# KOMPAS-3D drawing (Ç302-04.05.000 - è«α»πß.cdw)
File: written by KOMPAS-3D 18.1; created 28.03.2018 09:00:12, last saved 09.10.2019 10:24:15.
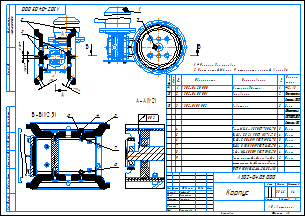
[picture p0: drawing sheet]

Sheet 1: A3, landscape

Document properties: Автор: Милов; Полное имя файла: ..\3Д ПВХ\А302-01.05.000 - Корпус.a3d; Масса: 33.4594

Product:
- Part/product: (unnamed)
  - Component: Болт М8-6gx35 ГОСТ 7805-70  | pos. 4  | Раздел спецификации: Стандартные изделия; Примечание: Нерж.
  - Component: Ловитель  | designation А302-01.05.002  | pos. 3  | Раздел спецификации: Детали; Форматы листов документа: А3; Примечание: Заим. / Фторопласт-4  / ГОСТ 10007-80 Е / Стержень @2~50
  - Component: Основание  | designation А302-04.05.001  | pos. 2  | Раздел спецификации: Детали; Форматы листов документа: А3; Примечание: Полипропилен / Стержень @2~300
  - Component: Мотор-редуктор  | designation А302-04.20.000  | pos. 1  | Раздел спецификации: Сборочные единицы; Форматы листов документа: 2xA3; Примечание: *)2xA3
  - Component: Шайба C.8.21 ГОСТ 11371-78  | pos. 5  | Раздел спецификации: Стандартные изделия; Примечание: Нерж.
  - Component: Шайба C 8.04.019 ГОСТ 6958-78  | pos. 6  | Раздел спецификации: Стандартные изделия; Примечание: Нерж.
  - Component: Шайба 8 30Х13 019 ГОСТ 6402-70  | pos. 7  | Раздел спецификации: Стандартные изделия; Примечание: Нерж.
  - Component: Гайка М8-6H.5.019 ГОСТ 5915-70  | pos. 8  | Раздел спецификации: Стандартные изделия; Примечание: Нерж
  - Component: Винт с потайной головкой и  / шестигранным углублением под ключ / ГОСТ Р ИСО 10642-М4x20-8.8-A3J  | pos. 9  | Раздел спецификации: Стандартные изделия; Примечание: Нерж.

Title block, sheet 1: Наименование: Корпус; designation: А302-04.05.000; Масса: 33,46; scale: 1:4; Количество листов документа: 1; organisation: АО «Астерион»; Форматы листов документа: A3; stored path: Z:\Мембранные насосы\Мембранный электропривод\А302-00.00.000 - ASTRA-302 (МЭ200)\Чертежи\А302-00.05.000 - Корпус.cdw; Разработал: Лифлянд; Проверил: Борисенко; Т. контр.: Лучихин; Утвердил: Григорьева

Views: Разрез В-В, Разрез А-А, Разрез Б-Б
Referenced files in \\192.168.87.28\Konstructor_doc\Мембранные насосы\Мембранный электропривод\А302-00.00.000 - ASTRA-302 (МЭ200)\3Д ПВХ\Отработка\: А302-01.05.000 - Корпус.a3d, А302-01.20.000 - Мотор-редуктор.a3d, А302-01.05.002 - Ловитель.m3d, Упор-1.m3d, Фиксатор.m3d
Referenced files in C:\Program Files\ASCON\KOMPAS-3D v18\Libs\PartLib\DATA\VAULT\methods\kompas\3d\: PLib_Check_spring_rings_GOST_13942_911.m3d, PLib_Washer_1_712.m3d, PLib_Bolt_1_900.m3d, PLib_Washer_2_712.m3d, PLib_Nut_OST92_900.m3d, PLib_Screw_DIN_7984_1500.m3d, PLib_Key_prismatic_712.m3d, PLib_Screw_ISO_10642_1500.m3d
Referenced files in D:\Мембранные насосы\Мембранный электропривод\А302-00.00.000 - ASTRA-302 (МЭ200)\3Д ПВХ\: А302-01.20.002 - Эксцентрик.m3d, FB 063 .m3d, А302-04.35.004 - Стенка.m3d, А302-04.35.003 - Опора подшиника.m3d, А302-01.20.001 - Основание.m3d, А302-01.35.000 - Фланец.a3d, А302-01.05.000 - Корпус.a3d, А302-01.05.011 - Ловитель.m3d, А302-01.05.015 - Фиксатор.m3d
Referenced files in D:\Мембранные насосы\Мембранный электропривод\А302-00.00.000 - ASTRA-302 (МЭ200)\3Д\: А302-00.35.002 - Пластина.m3d, А302-00.35.001 - Труба 140х140х4.m3d, А302-00.20.004 - Вал.m3d, А302-00.20.003 - Ползун.m3d, А302-00.05.001 - Основание.m3d
Referenced files in D:\1 ПКИ 3D\1 Крепеж стандартный\Подшипник\: Подшипник 52х25х15 62052RSH SKF.m3d, Подшипник 80х40х18 6208-2RS1 SKF.m3d
Referenced files in D:\1 ПКИ 3D\Редуктора NMRW\Редукторы\: Редуктор NMRW 063.m3d, Червячный мотор-редуктор NMRV063 АИР80.a3d
Referenced files in Z:\Мембранные насосы\Мембранный электропривод\А302-00.00.000 - ASTRA-302 (МЭ200)\3Д ПВХ\: А302-01.20.000 - Мотор-редуктор.cdw
Referenced files in \\192.168.87.28\Konstructor_doc\Мембранные насосы\Мембранный электропривод\А302-00.00.000 - ASTRA-302 (МЭ200)\3Д ПВХ\: А302-01.05.002 - Ловитель.cdw, А302-01.05.001 - Основание.m3d, А302-01.05.001 - Основание.cdw, А302-01.05.012 - Фиксатор.m3d, А302-01.05.012 - Фиксатор.cdw, А302-01.05.014 - Упор.cdw, А302-01.05.011 - Ловитель.m3d, А302-01.05.011 - Ловитель.cdw, А302-01.05.015 - Фиксатор.m3d, А302-01.05.015 - Фиксатор.cdw, А302-01.20.002 - Эксцентрик.m3d
Referenced files in \\192.168.87.28\Konstructor_doc\1 ПКИ 3D\1 Крепеж стандартный\Подшипник\: Подшипник 80х40х18 6208-2RS1 SKF.m3d, Подшипник 52х25х15 62052RSH SKF.m3d
Referenced files in D:\Мембранные насосы\Мембранный электропривод\А302-00.00.000 - ASTRA-302 (МЭ200)\3Д ПВХ\Отработка\: А302-01.20.000 - Мотор-редуктор.a3d, А302-01.05.002 - Ловитель.m3d, Фиксатор.m3d, Упор-1.m3d
Referenced files in D:\1 ПКИ 3D\Двигатели\АИР\: Электродвигатель АИР 80А4 IM 3081 1,1кВт 1400 об..m3d
Referenced files in C:\Program Files\ASCON\KOMPAS-3D V16\Libs\PartLib\DATA\VAULT\Methods\kompas\3d\: PLib_Bolt_1_900.m3d
Referenced files in Z:\Мембранные насосы\Мембранный электропривод\А302-00.00.000 - ASTRA-302 (МЭ200)\3Д\: А302-00.20.002 - Эксцентрик.m3d
Referenced files in C:\Program Files\ASCON\KOMPAS-3D V16\Libs\PartLib\DATA\vault\Methods\Kompas\3D\: PLib_Check_spring_rings_GOST_13942_911.m3d, PLib_Washer_2_712.m3d, PLib_Washer_1_712.m3d, PLib_Screw_DIN_7984_1500.m3d
Referenced files in \\192.168.87.28\Konstructor_doc\Мембранные насосы\Мембранный электропривод\А302-00.00.000 - ASTRA-302 (МЭ200)\3Д\: А302-00.20.004 - Вал.m3d, А302-00.35.001 - Труба 140х140х4.m3d, А302-00.35.002 - Пластина.m3d, А302-00.20.003 - Ползун.m3d
Referenced files in \\192.168.87.28\Konstructor_doc\1 ПКИ 3D\Двигатели\АИР\: Электродвигатель АИР 80А4 IM 3081 1,1кВт 1400 об..m3d
Referenced files in \\192.168.87.28\Konstructor_doc\1 ПКИ 3D\Редуктора NMRW\Редукторы\: Редуктор NMRW 063.m3d
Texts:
  Мотор-редуктор
  @100~)2xA3
  Ловитель
  Основание
  Шайба C.8.21 ГОСТ 11371-78
  Крепежное изделие ГОСТ
  Шайба
  ГОСТ
  нерж.
  Сталь 12Х18Н10Т ГОСТ 5632-72
  Шайба C 8 ГОСТ 6958-78
  Сталь 20 ГОСТ 1050-2013
  Шайба C 8.04.019 ГОСТ 6958-78
  Шайба 8 ГОСТ 6402-70
  Сталь 30Х13 ГОСТ 5632-72
  Шайба 8 30Х13 019 ГОСТ 6402-70
  Болт М8-6gx30 ГОСТ 7805-70
  Болт
  Болт М8-6gx30.58.019 ГОСТ 7805-70
  Гайка М8-6H ГОСТ 5915-70
  Гайка
  Гайка М8-6H.5.019 ГОСТ 5915-70
  Подшипник 80х40х18 6208-2RS1 SKF
  Подшипник
  SKF
  Фиксатор
  Упор
  Шайба C.5.21 ГОСТ 11371-78
  Шайба 5 ГОСТ 6402-70
  Винт с цилиндрической головкой
  и шестигранным углублением под ключ
  ГОСТ Р ИСО  4762-М5 x 16
  Винт с цилиндрической головкой и шестигранным углублением под ключ
  Р ИСО
  Сталь
  Шайба 5 30Х13 019 ГОСТ 6402-70
  Винт с цилиндрической головкой и шестигранным углублением под ключ ГОСТ Р ИСО  4762-М5 x 16-6.8-A9J
  ГОСТ Р ИСО  4762-М5 x 12
  Винт с цилиндрической головкой и шестигранным углублением под ключ ГОСТ Р ИСО  4762-М5 x 12-6.8-A9J
  Винт с потайной головкой
  ГОСТ Р ИСО  10642-М4 x 20
  Винт с потайной головкой и шестигранным углублением под ключ
  Винт с потайной головкой и шестигранным углублением под ключ ГОСТ Р ИСО  10642-М4 x 20-8.8-A3J
  ГОСТ Р ИСО  4762-М8 x 45
  Винт с цилиндрической головкой и шестигранным углублением под ключ ГОСТ Р ИСО  4762-М8 x 45-6.8-A9J
  ГОСТ Р ИСО  4762-М8 x 35
  Винт с цилиндрической головкой и шестигранным углублением под ключ ГОСТ Р ИСО  4762-М8 x 35-6.8-A9J
  Кольцо A40.65Г ГОСТ 13942-86
  Кольцо
  Сталь 65Г ГОСТ 14959-79
  Винт
  потайной
  головкой
  шестигранным
  углублением
  под
  ключ
  ИСО
  цилиндрической
  *)2xA3
  Полипропилен
  Стержень  300
  Полипропилен / Стержень @2~300
  Заим.
  Фторопласт-4
  ГОСТ 10007-80 Е
  Стержень  50
  Заим. / Фторопласт-4  / ГОСТ 10007-80 Е / Стержень @2~50
  Болт М8-6gx35 ГОСТ 7805-70
  Нерж.
  Нерж
  Винт с потайной головкой и
  шестигранным углублением под ключ
  ГОСТ Р ИСО 10642-М4x20-8.8-A3J
  Электродвигатель / АИР 80А4 IM 3081 1,1кВт 1400 об/мин
  Редуктор NMRW 063
  Мотор-редуктор / NMRV063 N P(кВт) V5 / P(мощн./дв.), i(передат. отн.) см. заказ
  Пластина
  Труба 140х140х6
  Опора подшипника
  Стенка
  Фланец
  Эксцентрик
  Кольцо A25.65Г ГОСТ 13942-86
  Подшипник 52х25х15 62052RSH SKF
  Вал
  Ползун
  Шайба C.6.21 ГОСТ 11371-78
  Болт М6-6gx40 ГОСТ 7805-70
  Шайба 6 30Х13 019 ГОСТ 6402-70
  Гайка М6-6H.21.12Х18Н10Т ГОСТ 5915-70
  Винт с цилиндрической головкой и шестигранным углублением под ключ ГОСТ Р ИСО 4762 - М8 x 25 - A2-70
  Гайка М8-6H.21.12Х18Н10Т ГОСТ 5915-70
  Шпонка 8x7x90 ГОСТ 23360-78
  FB 063
  Винт с цилиндрической головкой и шестигранным углублением под ключ ГОСТ Р ИСО 4762-М8 x 25-A2-70
  Болт М8-6gx35.58.019 ГОСТ 7805-70
  Винт с потайной головкой и шестигранным углублением под ключГОСТ Р ИСО 10642-М4x20-8.8-A3J
Dimensions and other numbers on the sheet: 0,02; 4; 1; 3; 2; 20; 21; 40Х; 019; 18; 8; 04; 17; 58; 30Х13; 14; 5; 6; 19; 16; 11; 6.8; 10; 9; 8.8; 13; 12; 15; 65Г; 7; 34; 0; 46; 42; 54; 49; 44; 30; 31; 40; 51; 53; 41; 1:4; 33,46

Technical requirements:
  *Размеры для справок.
  Винт потай М4 поз. 9 стопорить краской в резьбу.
